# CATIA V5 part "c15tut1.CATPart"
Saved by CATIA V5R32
Part number: Part1
Bounding box of the stored display mesh (mm): x -21 to 122, y 0 to 45, z -43 to 1
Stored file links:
  D:\PROJECTS\Project 2022\CATIA V5 6R 2022\Resources\Tutorial Files\c15_catia_v5_6r2022_tut\c15tut1.CATPart
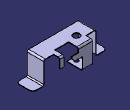
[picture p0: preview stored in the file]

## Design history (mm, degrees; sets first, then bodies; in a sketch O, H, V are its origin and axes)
SheetMetalParameters1: Thickness 1, BendRadius 2, KFactor 0.400515 {= log(min(100,max(20*SheetMetalParameters1.BendRadius,SheetMetalParameters1.Thickness)/SheetMetalParameters1.Thickness))/log(100)/2}, ReliefRadialLength 1, ReliefAxialLength 2, MinimumBendRadius 0
Body1 (main body)
  Sketch1 on xy-plane, origin (0, 0, 0), H (1, 0, 0), V (0, 1, 0)
    line L1 (0, 0) -> (101, 0)
    line L2 (101, 0) -> (101, 32)
    line L3 (101, 32) -> (82, 32)
    line L4 (82, 32) -> (82, 44)
    line L5 (82, 44) -> (74, 44)
    line L6 (74, 44) -> (74, 26)
    line L7 (74, 26) -> (47, 26)
    line L8 (47, 26) -> (47, 44)
    point P8 (47, 44)
    line L9 (47, 44) -> (20, 44)
    line L10 (20, 44) -> (20, 32)
    point P10 (20, 32)
    line L11 (20, 32) -> (0, 32)
    point P11 (0, 32)
    line L12 (0, 32) -> (0, 0)
    length L1 = 101
    length L2 = 32
    length L3 = 19
    length L5 = 8
    distance L1 L5 = 44
    distance L7 L1 = 26
    length L11 = 20
    length L9 = 27
    horizontal: L1 H, L3 H, L5 H, L7 H, L9 H, L11 H
    vertical: L2 V, L4 V, L6 V, L8 V, L10 V, L12 V
    coincidence: P8 L5, P10 L3, P11 V
  Wall1: Thickness 1, Profile Sketch1
  Flange1: Guide edge [face of Wall1 | face of Wall1], Angle 90, KFacteur 0.400515 {= log(min(100,max(20*Flange1.Radius,SheetMetalParameters1.Thickness)/SheetMetalParameters1.Thickness))/log(100)/2}, Length 44, Radius 2
  Flange2: Guide edge [face of Wall1 | face of Wall1], Angle 90, KFacteur 0.400515 {= log(min(100,max(20*Flange2.Radius,SheetMetalParameters1.Thickness)/SheetMetalParameters1.Thickness))/log(100)/2}, Length 44, Radius 2
  Flange3: Guide edge [face of Flange2 | face of Flange2], Angle 90, KFacteur 0.400515 {= log(min(100,max(20*Flange3.Radius,SheetMetalParameters1.Thickness)/SheetMetalParameters1.Thickness))/log(100)/2}, Length 22, Radius 2
  Flange4: Guide edge [face of Flange1 | face of Flange1], Angle 90, KFacteur 0.400515 {= log(min(100,max(20*Flange4.Radius,SheetMetalParameters1.Thickness)/SheetMetalParameters1.Thickness))/log(100)/2}, Length 22, Radius 2
  Sketch2 on face of Wall1, origin (47, 44, 0), H (-1, 0, 0), V (0, 0, 1)
    point P1 (0, 1)
    line L1 (0, 1) -> (0, -8)
    line L2 (0, -8) -> (-13, -8)
    line L3 (-13, -8) -> (-13, -18)
    line L4 (-13, -18) -> (8, -18)
    line L5 (8, -18) -> (8, -42)
    line L6 (8, -42) -> (27, -42)
    line L7 (27, -42) -> (27, 1)
    line L8 (27, 1) -> (0, 1)
    reference projected line E1 (27, 0) -> (27, 1) from edge [face of Wall1 | face of Wall1]
    reference projected line E2 (0, 1) -> (27, 1) from edge [face of Wall1 | face of Wall1]
    length L6 = 19
    length L7 = 43
    length L3 = 10
    distance L4 L8 = 19
    distance L3 L7 = 40
    coincidence: P1 V, L7 E1, L8 E2
    horizontal: L2 H, L4 H, L6 H
    vertical: L3 V, L5 V, L7 V, L1 V
  d_NewWallOnEdge1: NewWallOnEdge_Edge edge [face of Wall1 | face of Wall1], KFacteur 0.400515 {= log(min(100,max(20*d_NewWallOnEdge1.Radius,SheetMetalParameters1.Thickness)/SheetMetalParameters1.Thickness))/log(100)/2}, NewWallOnEdge_WallProfile Sketch2, NewWallOnEdge_Length 27, NewWallOnEdge_HeightLimitOffset 0, NewWallOnEdge_WidthOffset1 0, NewWallOnEdge_WidthOffset2 0, NewWallOnEdge_Angle 0, NewWallOnEdge_BendRadiusValue 2 {= SheetMetalParameters1.BendRadius}, NewWallOnEdge_BendTable SheetMetalParameters1
  Flange5: Guide edge [face of Wall1 | face of Wall1], Angle 90, KFacteur 0.400515 {= log(min(100,max(20*Flange5.Radius,SheetMetalParameters1.Thickness)/SheetMetalParameters1.Thickness))/log(100)/2}, Length 19, Radius 2
  Flange6: Guide edge [face of d_NewWallOnEdge1 | face of d_NewWallOnEdge1], Angle 90, KFacteur 0.400515 {= log(min(100,max(20*Flange6.Radius,SheetMetalParameters1.Thickness)/SheetMetalParameters1.Thickness))/log(100)/2}, Length 30, Radius 2
  Sketch3 on face of Wall1, origin (29.3791, 35.4737, 1), H (1, 0, 0), V (0, 1, 0)
    point P1 (-0.3791, -12.4737)
    reference projected line E1 (30.6209, 9.5263) -> (17.6209, 9.5263) from edge [face of d_NewWallOnEdge1 | face of d_NewWallOnEdge1]
    reference projected line E2 (-9.3791, 8.5263) -> (-9.3791, -3.4737) from edge [face of Wall1 | face of Wall1]
    distance P1 E1 = 22
    distance E2 P1 = 9
  Hole1: placed by Sketch3, at (29, 23, 1) direction (0, 0, -1), diameter 13, through (limit type 6)
  Sketch4 on face of Flange6, origin (31.6177, 25.4906, -41), H (1, 0, 0), V (0, 1, 0)
    point P1 (-2.6177, -2.4906)
    reference projected circle E1 centre (-2.6177, -2.4906) radius 6.5 from edge [face of Wall1 | face of Hole1]
    concentricity: P1 E1
  Hole2: placed by Sketch4, at (29, 23, -41) direction (0, 0, -1), diameter 8, through (limit type 6)
  Corner1: CornerChamferEdges (edge [face of Flange3 | face of Flange3]; edge [face of Flange3 | face of Flange3]; edge [face of Flange4 | face of Flange4]; edge [face of Flange4 | face of Flange4]), CornerRadius 7
  Corner2: CornerChamferEdges (edge [face of Wall1 | face of Wall1]; edge [face of Wall1 | face of Wall1]; edge [face of d_NewWallOnEdge1 | face of d_NewWallOnEdge1]; edge [face of Wall1 | face of Wall1]; edge [face of d_NewWallOnEdge1 | face of d_NewWallOnEdge1]; edge [face of Wall1 | face of Wall1]), CornerRadius 2
  Chamfer1: CornerChamferEdges edge [face of d_NewWallOnEdge1 | face of d_NewWallOnEdge1], ChamferAngle 45, ChamferLength1 6, ChamferLength2 0.5, ChamferPropagation 1, ChamferReverse false, ChamferType 1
